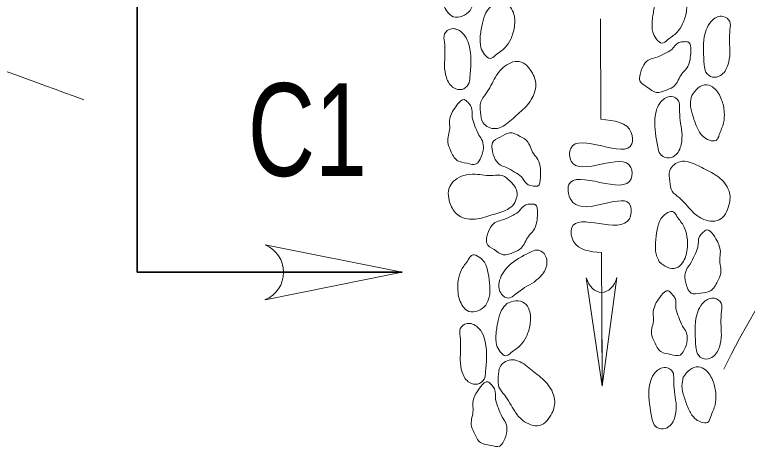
# Model space of a CAD drawing. Extents: x 1043.1 to 1101.1, y 672.4 to 716.4.
# Drawn here: x 1053.768 to 1055.663, y 707.808 to 708.927 of the extents above; entities that cross this region are included whole.
import ezdxf
from ezdxf.enums import TextEntityAlignment as Align

# ---------------------------------------------------------------- set-up
doc = ezdxf.new("R2010")
doc.units = 0
doc.header["$LTSCALE"] = 0.064
doc.layers.add('1', color=7, linetype='Continuous', lineweight=13)

msp = doc.modelspace()

# ---------------------------------------------------------------- linework, layer by layer
at = {"layer": '1', "lineweight": 35}
for p, q in [((1054.0845, 708.77808), (1054.0845, 709.07692)), ((1054.0845, 708.77808), (1054.0845, 708.261)), ((1054.0845, 708.261), (1054.76975, 708.261))]:
    msp.add_line(p, q, dxfattribs=at)
at = {"layer": '1'}
for p, q in [((1055.28425, 708.65708), (1055.28292, 708.91633)), ((1055.28742, 707.96642), (1055.28575, 708.31192)), ((1055.28625, 708.20933), (1055.28742, 707.96642)), ((1055.28642, 708.13925), (1055.28742, 707.96642))]:
    msp.add_line(p, q, dxfattribs=at)
for points in [[(1054.41575, 708.33183), (1054.76975, 708.261), (1054.41575, 708.19025), (1054.41583, 708.19033)], [(1055.32567, 708.24725), (1055.28742, 707.96642), (1055.24642, 708.24683), (1055.24642, 708.24675)]]:
    msp.add_lwpolyline(points, dxfattribs=at)
msp.add_arc((1054.38712, 708.26111), 0.0764, 292.08605, 67.91218, dxfattribs=at)
for centre, major_axis, ratio, start_param, end_param in [((1057.14583, 707.12282), (0, -1.90348), 0.916763, 3.4772218, 4.2269565), ((1055.28594, 708.2698), (0.00023, -0.06058), 0.705058, 5.0991244, 7.4697376)]:
    msp.add_ellipse(centre, major_axis=major_axis, ratio=ratio, start_param=start_param, end_param=end_param, dxfattribs=at)
for points in [[(1047.08833, 709.4815), (1047.81092, 709.394), (1049.167, 709.30692), (1050.51275, 709.22058), (1051.84692, 709.13492), (1053.14792, 708.968), (1053.9465, 708.70742)], [(1054.94633, 708.93792), (1054.95458, 708.95875), (1054.95575, 708.98725), (1054.95183, 709.0205), (1054.942, 709.04875), (1054.9285, 709.06233), (1054.912, 709.068), (1054.90042, 709.05533), (1054.88283, 709.02925), (1054.87458, 709.00308), (1054.874, 708.9695), (1054.8865, 708.93508), (1054.90233, 708.92208), (1054.9255, 708.9235), (1054.94633, 708.93792)], [(1055.44483, 708.989), (1055.43125, 708.97192), (1055.42233, 708.945), (1055.41692, 708.91208), (1055.4185, 708.88192), (1055.42775, 708.86433), (1055.44217, 708.85375), (1055.4565, 708.86208), (1055.48058, 708.88142), (1055.4955, 708.9035), (1055.50525, 708.9355), (1055.50275, 708.97233), (1055.49108, 708.98992), (1055.4685, 708.996), (1055.44483, 708.989)], [(1055.00008, 708.94933), (1054.98658, 708.93208), (1054.97767, 708.90533), (1054.97225, 708.87242), (1054.97392, 708.84208), (1054.98317, 708.82458), (1054.9975, 708.81392), (1055.01175, 708.82233), (1055.036, 708.8415), (1055.05083, 708.86375), (1055.06033, 708.89583), (1055.058, 708.93258), (1055.04625, 708.95008), (1055.02367, 708.95633), (1055.00008, 708.94933)], [(1055.61808, 708.82792), (1055.61258, 708.79675), (1055.59342, 708.76983), (1055.57283, 708.76592), (1055.556, 708.77883), (1055.55167, 708.79742), (1055.55167, 708.87008), (1055.57283, 708.91333), (1055.59992, 708.92283), (1055.61742, 708.90958), (1055.61808, 708.88908), (1055.61808, 708.82792)], [(1054.87933, 708.79608), (1054.88458, 708.7645), (1054.904, 708.73775), (1054.9245, 708.734), (1054.94117, 708.74692), (1054.94533, 708.7655), (1054.94533, 708.83792), (1054.9245, 708.88142), (1054.89742, 708.89075), (1054.87983, 708.8775), (1054.87933, 708.857), (1054.87933, 708.79608)], [(1055.51483, 708.81133), (1055.51667, 708.83408), (1055.51075, 708.85633), (1055.50025, 708.85742), (1055.48617, 708.8555), (1055.46725, 708.83708), (1055.44817, 708.82608), (1055.42667, 708.81633), (1055.4105, 708.81175), (1055.396, 708.79858), (1055.38542, 708.77225), (1055.38525, 708.75625), (1055.404, 708.73983), (1055.42742, 708.72633), (1055.45542, 708.73283), (1055.47433, 708.74333), (1055.49333, 708.77392), (1055.50567, 708.78792), (1055.51483, 708.81133)], [(1055.10925, 708.71692), (1055.11558, 708.74125), (1055.10717, 708.77592), (1055.07317, 708.80608), (1055.031, 708.79033), (1055.01133, 708.76575), (1054.98675, 708.72233), (1054.97333, 708.7015), (1054.97283, 708.675), (1054.97958, 708.64758), (1055.01158, 708.63258), (1055.031, 708.639), (1055.06517, 708.66633), (1055.09792, 708.69875), (1055.10925, 708.71692)], [(1055.51908, 708.71842), (1055.51583, 708.69608), (1055.52117, 708.66833), (1055.53242, 708.63708), (1055.54842, 708.61225), (1055.56483, 708.60275), (1055.58192, 708.60183), (1055.59042, 708.61708), (1055.60142, 708.64742), (1055.60333, 708.67492), (1055.59625, 708.70742), (1055.57667, 708.7375), (1055.55808, 708.74583), (1055.53592, 708.73808), (1055.51908, 708.71842)], [(1054.90025, 708.67708), (1054.91333, 708.69542), (1054.93108, 708.7075), (1054.93958, 708.70075), (1054.94883, 708.68883), (1054.9515, 708.66133), (1054.9585, 708.63925), (1054.96842, 708.61592), (1054.9775, 708.60092), (1054.98008, 708.58042), (1054.97167, 708.55325), (1054.96183, 708.54133), (1054.93792, 708.54308), (1054.91225, 708.55042), (1054.8955, 708.57558), (1054.88825, 708.59725), (1054.89308, 708.63383), (1054.8925, 708.65308), (1054.90025, 708.67708)], [(1055.49392, 708.62358), (1055.49175, 708.59158), (1055.4755, 708.56275), (1055.45533, 708.55683), (1055.4375, 708.56708), (1055.43142, 708.58508), (1055.424, 708.6575), (1055.44033, 708.70292), (1055.46633, 708.7155), (1055.48508, 708.70458), (1055.48775, 708.68433), (1055.49392, 708.62358)], [(1055.28575, 708.31192), (1055.21342, 708.341), (1055.20883, 708.37692), (1055.35775, 708.39933), (1055.361, 708.43258), (1055.212, 708.44175), (1055.20117, 708.48775), (1055.36275, 708.50308), (1055.36158, 708.53242), (1055.20717, 708.54833), (1055.206, 708.5815), (1055.36408, 708.59308), (1055.36283, 708.62233), (1055.28425, 708.65708)], [(1055.12808, 708.52883), (1055.12792, 708.50583), (1055.12042, 708.48408), (1055.11, 708.48408), (1055.09608, 708.48733), (1055.07858, 708.50775), (1055.06083, 708.52033), (1055.04, 708.53233), (1055.02442, 708.53833), (1055.01108, 708.55308), (1055.00258, 708.58025), (1055.00375, 708.59633), (1055.02367, 708.61075), (1055.04817, 708.62175), (1055.07567, 708.6125), (1055.09333, 708.60025), (1055.10983, 708.56783), (1055.12108, 708.55308), (1055.12808, 708.52883)], [(1055.60392, 708.49275), (1055.61583, 708.47075), (1055.6155, 708.435), (1055.58967, 708.3965), (1055.545, 708.40025), (1055.52017, 708.41875), (1055.4865, 708.45425), (1055.46867, 708.4705), (1055.46233, 708.49592), (1055.4625, 708.52442), (1055.49008, 708.5475), (1055.51017, 708.54675), (1055.54967, 708.5295), (1055.58883, 708.507), (1055.60392, 708.49275)], [(1054.939, 708.399), (1054.91725, 708.40708), (1054.89608, 708.43475), (1054.893, 708.4825), (1054.92933, 708.51133), (1054.95917, 708.5145), (1055.00592, 708.51133), (1055.02908, 708.51133), (1055.04925, 708.49642), (1055.06575, 708.47458), (1055.05867, 708.43742), (1055.04267, 708.42383), (1055.00242, 708.40925), (1054.95917, 708.3985), (1054.939, 708.399)], [(1055.11858, 708.3915), (1055.12025, 708.41433), (1055.11425, 708.4365), (1055.10392, 708.43758), (1055.08967, 708.43575), (1055.07092, 708.41733), (1055.052, 708.40633), (1055.03033, 708.39658), (1055.01425, 708.39192), (1054.99975, 708.37858), (1054.98925, 708.35233), (1054.98883, 708.33633), (1055.00775, 708.31992), (1055.03117, 708.30658), (1055.05925, 708.31292), (1055.07783, 708.32342), (1055.09683, 708.354), (1055.10933, 708.368), (1055.11858, 708.3915)], [(1055.43525, 708.28833), (1055.42683, 708.30908), (1055.42567, 708.33742), (1055.42958, 708.37075), (1055.43942, 708.399), (1055.45308, 708.41283), (1055.46958, 708.41842), (1055.481, 708.40575), (1055.49875, 708.3795), (1055.50683, 708.35333), (1055.50742, 708.31983), (1055.495, 708.28558), (1055.47908, 708.2725), (1055.45592, 708.27392), (1055.43525, 708.28833)], [(1055.58675, 708.33858), (1055.575, 708.35758), (1055.55775, 708.371), (1055.54892, 708.36475), (1055.53908, 708.35342), (1055.53492, 708.32633), (1055.52642, 708.30483), (1055.51525, 708.2825), (1055.50533, 708.26775), (1055.50158, 708.2475), (1055.5085, 708.21983), (1055.51742, 708.20708), (1055.54158, 708.20725), (1055.56758, 708.21275), (1055.58567, 708.237), (1055.59433, 708.258), (1055.5915, 708.29492), (1055.59325, 708.314), (1055.58675, 708.33858)], [(1054.98683, 708.17592), (1054.99525, 708.19675), (1054.9965, 708.22508), (1054.9925, 708.25833), (1054.98275, 708.28683), (1054.96908, 708.3005), (1054.95258, 708.30608), (1054.94108, 708.29342), (1054.92342, 708.26725), (1054.91525, 708.24092), (1054.91467, 708.2075), (1054.92717, 708.173), (1054.943, 708.16008), (1054.96625, 708.1615), (1054.98683, 708.17592)], [(1055.11117, 708.23575), (1055.13333, 708.2565), (1055.14458, 708.28825), (1055.137, 708.30933), (1055.11858, 708.31858), (1055.10167, 708.31308), (1055.0445, 708.27625), (1055.02092, 708.2345), (1055.02733, 708.20425), (1055.04625, 708.1945), (1055.063, 708.20433), (1055.11117, 708.23575)], [(1055.42742, 708.18258), (1055.44033, 708.201), (1055.45842, 708.21325), (1055.46667, 708.20608), (1055.47583, 708.19433), (1055.47833, 708.16683), (1055.48558, 708.14483), (1055.4955, 708.1215), (1055.50467, 708.10633), (1055.50717, 708.08592), (1055.49875, 708.05883), (1055.48892, 708.04692), (1055.465, 708.04858), (1055.43933, 708.05583), (1055.42275, 708.08108), (1055.41517, 708.10275), (1055.42017, 708.13933), (1055.41958, 708.15875), (1055.42742, 708.18258)], [(1055.59608, 708.09908), (1055.59075, 708.06783), (1055.5715, 708.04092), (1055.551, 708.03725), (1055.53425, 708.05), (1055.53008, 708.0685), (1055.53008, 708.14133), (1055.551, 708.1845), (1055.57808, 708.194), (1055.59558, 708.18083), (1055.59608, 708.16033), (1055.59608, 708.09908)], [(1055.04075, 708.18033), (1055.02717, 708.16308), (1055.01842, 708.13633), (1055.013, 708.10333), (1055.0145, 708.07308), (1055.02367, 708.05575), (1055.03817, 708.045), (1055.05217, 708.05342), (1055.07642, 708.0725), (1055.09133, 708.09483), (1055.101, 708.12683), (1055.09867, 708.16333), (1055.08692, 708.18108), (1055.06433, 708.18733), (1055.04075, 708.18033)], [(1054.92, 708.03408), (1054.92525, 708.00258), (1054.9445, 707.97575), (1054.96517, 707.972), (1054.98192, 707.98475), (1054.986, 708.00333), (1054.986, 708.07592), (1054.96517, 708.11933), (1054.93792, 708.12858), (1054.92058, 708.1155), (1054.92, 708.09492), (1054.92, 708.03408)], [(1055.157, 707.95583), (1055.16442, 707.93208), (1055.15767, 707.89683), (1055.12525, 707.86492), (1055.08192, 707.87825), (1055.06125, 707.90183), (1055.03467, 707.94392), (1055.02058, 707.96392), (1055.01875, 707.99033), (1055.02425, 708.01808), (1055.05575, 708.03475), (1055.07517, 708.02942), (1055.11058, 708.00392), (1055.14492, 707.97325), (1055.157, 707.95583)], [(1055.47858, 707.92308), (1055.4765, 707.891), (1055.46017, 707.86208), (1055.44008, 707.85608), (1055.42208, 707.8665), (1055.41617, 707.8845), (1055.4085, 707.95692), (1055.425, 708.00242), (1055.45108, 708.015), (1055.46975, 708.00408), (1055.47242, 707.98383), (1055.47858, 707.92308)], [(1055.49725, 707.98975), (1055.49392, 707.96733), (1055.49933, 707.93942), (1055.51075, 707.90833), (1055.52667, 707.8835), (1055.54308, 707.87392), (1055.56025, 707.873), (1055.56842, 707.88833), (1055.57958, 707.9185), (1055.58158, 707.94608), (1055.5745, 707.97858), (1055.55483, 708.00875), (1055.5365, 708.017), (1055.51408, 708.00925), (1055.49725, 707.98975)], [(1054.96092, 707.94775), (1054.97392, 707.96592), (1054.99183, 707.97808), (1055.00008, 707.97108), (1055.00933, 707.95933), (1055.01183, 707.93183), (1055.01908, 707.90975), (1055.029, 707.88658), (1055.03817, 707.87133), (1055.04067, 707.85083), (1055.03225, 707.82375), (1055.02242, 707.81183), (1054.99842, 707.81342), (1054.97283, 707.82083), (1054.95625, 707.84608), (1054.94883, 707.86775), (1054.95367, 707.90433), (1054.95308, 707.92383), (1054.96092, 707.94775)]]:
    msp.add_spline(points, degree=3, dxfattribs=at)

# ---------------------------------------------------------------- texts
at = {"layer": '1', "width": 0.75}
msp.add_text('C1', height=0.24, dxfattribs=at).set_placement((1054.52475, 708.51008), align=Align.CENTER)

doc.saveas('drawing.dxf')
